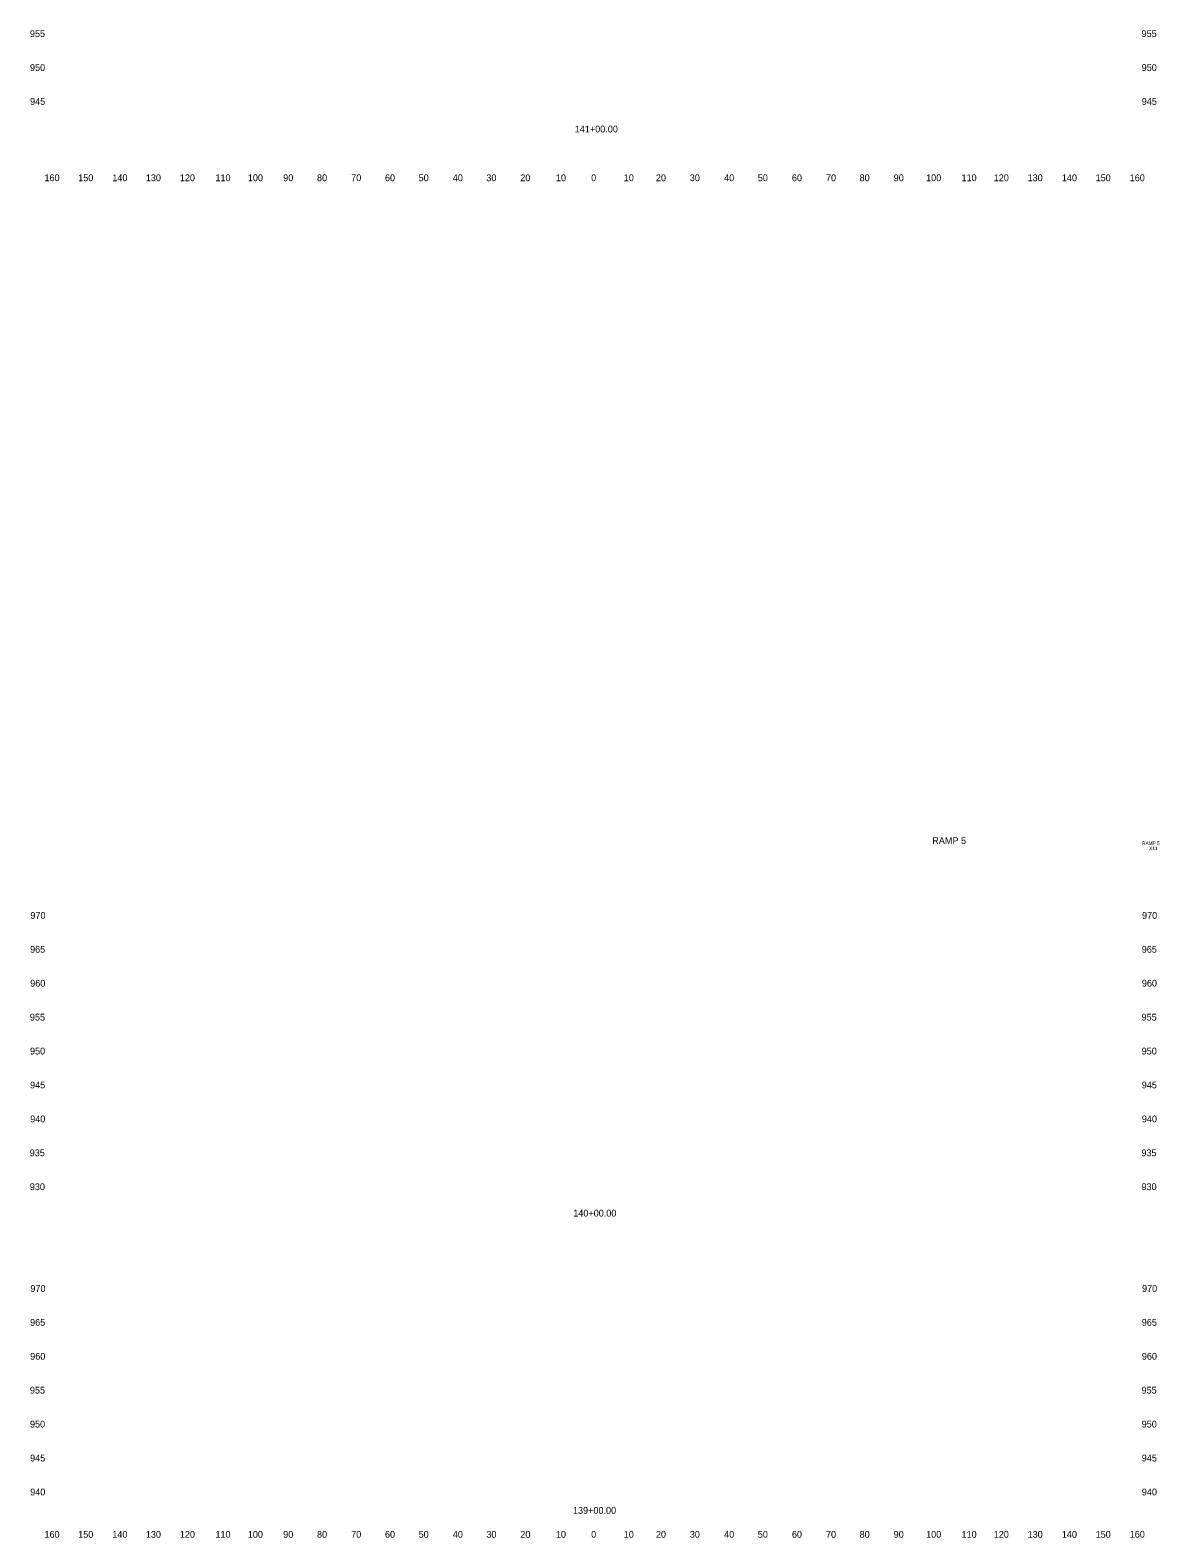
# Model space of a CAD drawing. Extents: x 4994 to 5842, y 4997 to 8804.
# Drawn here: x 5508.9 to 5841.7, y 4997.5 to 5442 of the extents above; entities that cross this region are included whole.
import ezdxf

# ---------------------------------------------------------------- set-up
doc = ezdxf.new("R2010")
doc.units = 0
for name, color, linetype in [('CLS_Search_Dist', 7, 'Continuous'), ('RD_XE_Ground', 7, 'Continuous'), ('UC_PD_Text', 7, 'Continuous')]:
    doc.layers.add(name, color=color, linetype=linetype)

msp = doc.modelspace()

# ---------------------------------------------------------------- texts
at = {"layer": 'CLS_Search_Dist'}
for s, p in [('955', (5508.8, 5440)), ('955', (5836.6, 5440)), ('950', (5508.83, 5430)), ('950', (5836.63, 5430)), ('945', (5508.86, 5420)), ('945', (5836.66, 5420)), ('160', (5513.1, 5397.5)), ('150', (5523.04, 5397.5)), ('140', (5533.1, 5397.5)), ('130', (5542.99, 5397.5)), ('120', (5553.01, 5397.5)), ('110', (5563.51, 5397.5)), ('100', (5573.07, 5397.5)), ('90', (5583.5, 5397.5)), ('80', (5593.46, 5397.5)), ('70', (5603.54, 5397.5)), ('60', (5613.5, 5397.5)), ('50', (5623.43, 5397.5)), ('40', (5633.5, 5397.5)), ('30', (5643.39, 5397.5)), ('20', (5653.4, 5397.5)), ('10', (5663.91, 5397.5)), ('0', (5674.3, 5397.5)), ('0', (5674.3, 5397.5)), ('10', (5683.91, 5397.5)), ('20', (5693.4, 5397.5)), ('30', (5703.39, 5397.5)), ('40', (5713.5, 5397.5)), ('50', (5723.43, 5397.5)), ('60', (5733.5, 5397.5)), ('70', (5743.54, 5397.5)), ('80', (5753.46, 5397.5)), ('90', (5763.5, 5397.5)), ('100', (5773.07, 5397.5)), ('110', (5783.51, 5397.5)), ('120', (5793.01, 5397.5)), ('130', (5802.99, 5397.5)), ('140', (5813.1, 5397.5)), ('150', (5823.04, 5397.5)), ('160', (5833.1, 5397.5)), ('970', (5508.94, 5180)), ('970', (5836.74, 5180)), ('965', (5508.86, 5170)), ('965', (5836.66, 5170)), ('960', (5508.89, 5160)), ('960', (5836.69, 5160)), ('955', (5508.8, 5150)), ('955', (5836.6, 5150)), ('950', (5508.83, 5140)), ('950', (5836.63, 5140)), ('945', (5508.86, 5130)), ('945', (5836.66, 5130)), ('940', (5508.89, 5120)), ('940', (5836.69, 5120)), ('935', (5508.75, 5110)), ('935', (5836.55, 5110)), ('930', (5508.78, 5100)), ('930', (5836.58, 5100)), ('970', (5508.94, 5070)), ('970', (5836.74, 5070)), ('965', (5508.86, 5060)), ('965', (5836.66, 5060)), ('960', (5508.89, 5050)), ('960', (5836.69, 5050)), ('955', (5508.8, 5040)), ('955', (5836.6, 5040)), ('950', (5508.83, 5030)), ('950', (5836.63, 5030)), ('945', (5508.86, 5020)), ('945', (5836.66, 5020)), ('940', (5508.89, 5010)), ('940', (5836.69, 5010)), ('160', (5513.1, 4997.5)), ('150', (5523.04, 4997.5)), ('140', (5533.1, 4997.5)), ('130', (5542.99, 4997.5)), ('120', (5553.01, 4997.5)), ('110', (5563.51, 4997.5)), ('100', (5573.07, 4997.5)), ('90', (5583.5, 4997.5)), ('80', (5593.46, 4997.5)), ('70', (5603.54, 4997.5)), ('60', (5613.5, 4997.5)), ('50', (5623.43, 4997.5)), ('40', (5633.5, 4997.5)), ('30', (5643.39, 4997.5)), ('20', (5653.4, 4997.5)), ('10', (5663.91, 4997.5)), ('0', (5674.3, 4997.5)), ('0', (5674.3, 4997.5)), ('10', (5683.91, 4997.5)), ('20', (5693.4, 4997.5)), ('30', (5703.39, 4997.5)), ('40', (5713.5, 4997.5)), ('50', (5723.43, 4997.5)), ('60', (5733.5, 4997.5)), ('70', (5743.54, 4997.5)), ('80', (5753.46, 4997.5)), ('90', (5763.5, 4997.5)), ('100', (5773.07, 4997.5)), ('110', (5783.51, 4997.5)), ('120', (5793.01, 4997.5)), ('130', (5802.99, 4997.5)), ('140', (5813.1, 4997.5)), ('150', (5823.04, 4997.5)), ('160', (5833.1, 4997.5))]:
    msp.add_text(s, height=2, dxfattribs=at).set_placement(p)
at = {"layer": 'RD_XE_Ground'}
for s, p in [('141+00.00', (5669.46, 5411.86)), ('140+00.00', (5669.02, 5092.21)), ('139+00.00', (5668.94, 5004.56))]:
    msp.add_text(s, height=2, dxfattribs=at).set_placement(p)
at = {"layer": 'UC_PD_Text'}
for s, height, p in [('RAMP 5', 2, (5774.89, 5202.06)), ('RAMP 5', 1, (5836.78, 5201.8)), ('X11', 1, (5838.85, 5200.3))]:
    msp.add_text(s, height=height, dxfattribs=at).set_placement(p)

doc.saveas('drawing.dxf')
